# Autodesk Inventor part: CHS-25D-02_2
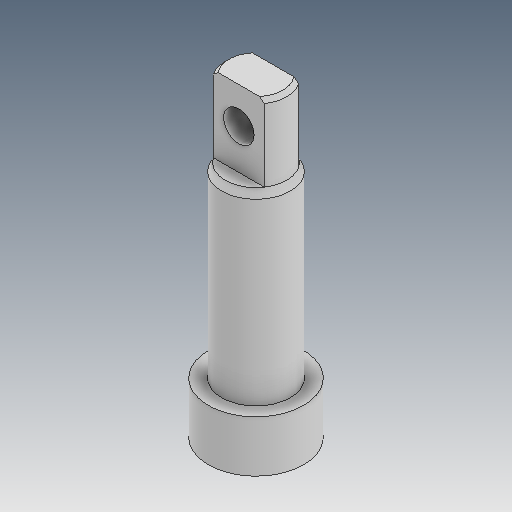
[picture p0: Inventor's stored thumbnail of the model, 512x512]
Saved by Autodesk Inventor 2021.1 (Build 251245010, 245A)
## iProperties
Created: 2019-04
Part Number: CHS-25D-02_2
Material: Ogólny
Document SubType Name: Modeling
Designer: user
Density: 1 g/cm^3
Appearance: Domyślna
Author: user
Revision Number: ÈÎºÎ
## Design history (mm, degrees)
feature "ÊäÈë1"
feature "ÊäÈë2"
node "Bryła1"
node "Bryła2"
